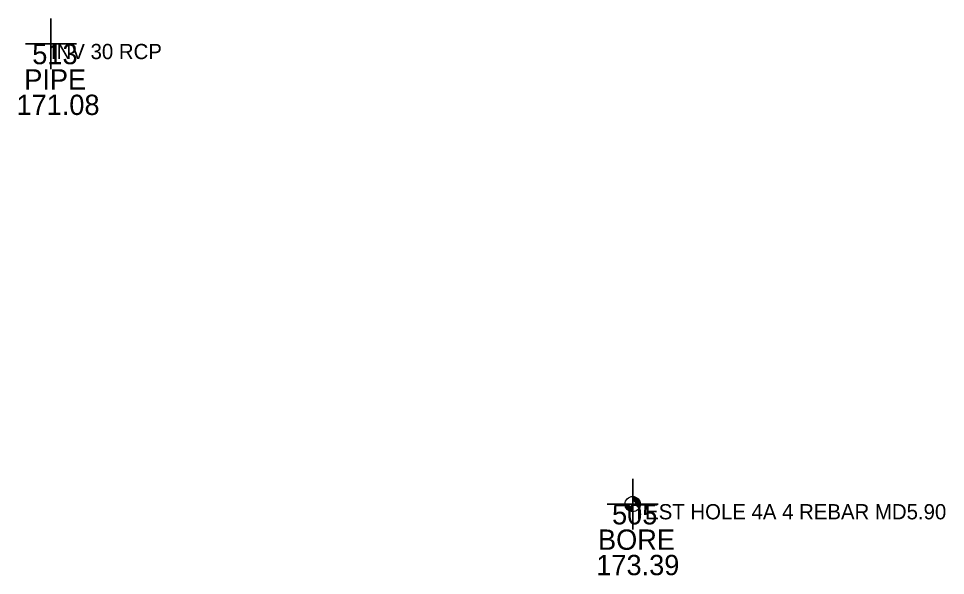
# Model space of a CAD drawing. Extents: x 1969314 to 1970910, y 795817 to 797766.
# Drawn here: x 1969602.2 to 1969693.5, y 797584.5 to 797639.4 of the extents above; entities that cross this region are included whole.
import ezdxf

# ---------------------------------------------------------------- set-up
doc = ezdxf.new("R2010")
doc.units = 0
for name, color, linetype in [('Level 63', 7, 'Continuous'), ('SV_Control_Boring', 7, 'Continuous'), ('SV_Control_Boring_Code', 7, 'Continuous'), ('SV_Control_Boring_Elev', 7, 'Continuous'), ('SV_Control_Boring_Name', 7, 'Continuous'), ('SV_Control_Boring_Shot', 7, 'Continuous'), ('SV_SD_Pipe_Code', 7, 'Continuous'), ('SV_SD_Pipe_Elev', 7, 'Continuous'), ('SV_SD_Pipe_Name', 7, 'Continuous'), ('SV_SD_Pipe_Shot', 7, 'Continuous')]:
    doc.layers.add(name, color=color, linetype=linetype)

msp = doc.modelspace()

# ---------------------------------------------------------------- linework, layer by layer
at = {"layer": 'SV_Control_Boring'}
for p, q in [((1969662.676, 797590.818), (1969662.676, 797592.318)), ((1969661.926, 797591.568), (1969663.426, 797591.568))]:
    msp.add_line(p, q, dxfattribs=at)
msp.add_circle((1969662.676, 797591.568), 0.75, dxfattribs=at)
for radius, start, end in [(0.693, 0.00006, 89.99948), (0.631, 0.00006, 89.99948), (0.569, 0.00006, 89.99948), (0.507, 0.00006, 89.99948), (0.445, 0.00006, 89.99948), (0.384, 0.00006, 89.99948), (0.322, 0.00006, 89.99948), (0.698, 179.99986, 270.00021), (0.635, 179.99986, 270.00021), (0.573, 179.99986, 270.00021), (0.51, 179.99986, 270.00021), (0.448, 179.99986, 270.00021), (0.385, 179.99986, 270.00021)]:
    msp.add_arc((1969662.676, 797591.568), radius, start, end, dxfattribs=at)
at = {"layer": 'SV_Control_Boring_Shot'}
msp.add_lwpolyline([(1969662.676, 797591.568), (1969662.676, 797594.068), (1969662.676, 797591.568), (1969660.176, 797591.568), (1969662.676, 797591.568), (1969662.676, 797589.068), (1969662.676, 797591.568), (1969665.176, 797591.568)], close=True, dxfattribs=at)
at = {"layer": 'SV_SD_Pipe_Shot'}
msp.add_lwpolyline([(1969605.392, 797636.9), (1969605.392, 797639.4), (1969605.392, 797636.9), (1969602.892, 797636.9), (1969605.392, 797636.9), (1969605.392, 797634.4), (1969605.392, 797636.9), (1969607.892, 797636.9)], close=True, dxfattribs=at)

# ---------------------------------------------------------------- texts
at = {"layer": 'Level 63'}
for s, p in [('INV 30 RCP', (1969605.392, 797635.4)), ('TEST HOLE 4A 4 REBAR MD5.90', (1969662.676, 797590.068))]:
    msp.add_text(s, height=1.5, dxfattribs=at).set_placement(p)
at = {"layer": 'SV_Control_Boring_Code'}
msp.add_text('BORE', height=2, dxfattribs=at).set_placement((1969659.263, 797587.068))
at = {"layer": 'SV_Control_Boring_Elev'}
msp.add_text('173.39', height=2, dxfattribs=at).set_placement((1969659.091, 797584.568))
at = {"layer": 'SV_Control_Boring_Name'}
msp.add_text('505', height=2, dxfattribs=at).set_placement((1969660.644, 797589.568))
at = {"layer": 'SV_SD_Pipe_Code'}
msp.add_text('PIPE', height=2, dxfattribs=at).set_placement((1969602.763, 797632.4))
at = {"layer": 'SV_SD_Pipe_Elev'}
msp.add_text('171.08', height=2, dxfattribs=at).set_placement((1969601.997, 797629.9))
at = {"layer": 'SV_SD_Pipe_Name'}
msp.add_text('513', height=2, dxfattribs=at).set_placement((1969603.552, 797634.9))

doc.saveas('drawing.dxf')
